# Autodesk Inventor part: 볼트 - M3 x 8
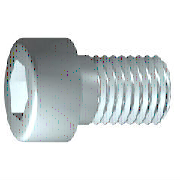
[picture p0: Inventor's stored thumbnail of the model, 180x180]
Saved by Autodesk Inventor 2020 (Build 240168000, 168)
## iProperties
Created: 2012-02
Part Number: 볼트 - M3 x 8
Material: 스테인리스강
Description: 6각 소켓 머리 캡 나사
Document SubType Name: Modeling
Standard: ISO 4762
Designer: mduedu
Standard Revision: Fourth edition 2004-03-01
Standards Organization: ISO
Language: ko-KR
Size Designation: M3 x 8
Categories: <MemberInstance><Categories><Category DisplayName="조임쇠" InternalName="e4da775c-781d-43d5-af7c-5136215cf5a6" Mnemonic="FSTN"><Category DisplayName="볼트" InternalN
Density: 8.08 g/cm^3
Mass: 0.955869 g
Surface Area: 1.83001 cm^2
Volume: 0.118301 cm^3
Appearance: 반광택
IsCustomPart: 0
Author: mduedu
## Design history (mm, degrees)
sketch "스케치1"
  geometry: L1 (-0.867, 0)-(8, 0); L2 (8, 0)-(8, 1.5); L3 (8, 1.5)-(1.25, 1.5); L4 (1.25, 1.5)-(0.943, 1.5); L5 (0.943, 1.5)-(0, 1.5); L6 (0, 1.5)-(0, 2.75); L7 (0, 2.75)-(-3, 2.75); L8 (-3, 2.75)-(-3, 1.443); L9 (-3, 1.443)-(-1.7, 1.443); L10 (-1.7, 1.443)-(-0.867, 0); L11 (-5.2, 0)-(10.2, 0) reference; L12 (0, -0.55)-(0, 3.3) reference; L13 (1.25, 1.5)-(0, 1.5)
  constraints: 22 end point, 6 parallel, 2 collinear, 2 perpendicular, 1 horizontal, 1 point on line
  dimensions: "d1" = 6.75 distance from line of L3.end L2 (= GEL); "d2" = 0.30683 distance of L4.end L3.end (computed from GAL); "d3" = 3 distance between parallel lines of L8 L6 (= KOH); "d4" = 1.3 distance of L8.end L9.end (= INTI); "d5" = 60 deg angle of L10 L1; "d6" = 3 diameter of L3 L1 (= GD); "d7" = 3 diameter of L5 L1 (= BDM); "d8" = 2.88675 diameter of L9 L1 (= 1.1547 x SW); "d9" = 5.5 diameter of L7 L1 (= KOD); "d26" = 8 distance between parallel lines of L12 L2 (= NLG)
revolve "본체" sketch "스케치1" stored, may be unused: angle "d10" = 90 deg
sketch "스케치2"
  geometry: L1 (0, -3.85)-(0, 3.85) reference; L2 (-3.85, 0)-(3.85, 0) reference; L3 (1.443, 0)-(0.722, -1.25); L4 (0.722, -1.25)-(-0.722, -1.25); L5 (-0.722, -1.25)-(-1.443, 0); L6 (-1.443, 0)-(-0.722, 1.25); L7 (-0.722, 1.25)-(0.722, 1.25); L8 (0.722, 1.25)-(1.443, 0); 2 further points
  constraints: 12 end point, 1 coincident, 1 horizontal alignment, 1 point on line, 12 other
extrude "슬롯" join sketch "스케치2" stored distance "d11" = 10; taper "d12" = 0 deg
workplane "Work Plane1"
fillet "Fillet2" dims "d30" = 0.1 (= R)
body "Solid1"
fillet "모깎기1" dims "d17" = 0.3 (= RR)
feature "스레드" dims "d13" = 6.75 (= GEL), "d14" = 0
chamfer "모따기1" distance "d15" = 0.30673 (= -0.5 x SPD + 0.5 x GD); stored, may be unused: second distance "d16" = 0.30673 (= GUL), angle "d27" = 45 deg
other parameters: "GD" = 3 [user parameter; used in 2 equation terms], "NLG" = 8 [user parameter; used in 1 equation term], "GEL" = 6.75 [user parameter; used in 2 equation terms], "KOD" = 5.5 [user parameter; used in 1 equation term], "KOH" = 3 [user parameter; used in 1 equation term], "INTI" = 1.3 [user parameter; used in 1 equation term], "GAL" = 0.30673 (= 0.61345 x PTC) [user parameter; used in 1 equation term], "GUL" = 0.30673 (= 0.61345 x PTC) [user parameter; used in 1 equation term], "BDM" = 3 (= NND) [user parameter; used in 1 equation term], "SW" = 2.5 [user parameter; used in 2 equation terms], "RR" = 0.3 [user parameter; used in 1 equation term], "SPD" = 2.38655 (= NND - 1.2269 x PTC) [user parameter; used in 1 equation term], "d19" = 0, "d28" = 0, "d29" = 0, "R" = 0.1 [user parameter; used in 1 equation term], "TOA" = 30 deg [user parameter], "GD1" = 2.38655 (= THREADDIA - 1.2269 x PTC) [user parameter], "THREADDIA" = 3 [user parameter; used in 1 equation term], "FAWI" = 45 deg [user parameter], "PTC" = 0.5 [user parameter; used in 5 equation terms], "NND" = 3 [user parameter; used in 2 equation terms], "E0" = 2.8875 (= 1.155 x SW) [user parameter]
